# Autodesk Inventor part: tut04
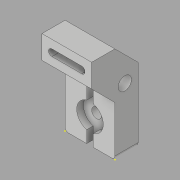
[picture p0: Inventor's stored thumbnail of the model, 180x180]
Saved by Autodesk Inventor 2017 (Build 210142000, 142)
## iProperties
Created: 2015-03
Part Number: tut04
Material: Generic
Document SubType Name: Modeling
Designer: Sandeep
Density: 1 g/cm^3
Appearance: Default
Author: Sandeep
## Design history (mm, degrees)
sketch "Sketch1"
  geometry: L1 (0, 0)-(0, 30); L2 (0, 30)-(-14, 44); L3 (-14, 44)-(-14, 58); L4 (-14, 58)-(0, 58); L5 (14, 44)-(14, 0); L6 (14, 0)-(0, 0); L7 (0, 58)-(14, 44)
  constraints: 14 end point, 3 parallel, 1 horizontal, 1 perpendicular, 1 vertical
  dimensions: "d0" = 14 distance between parallel lines of L5 L1; "d1" = 14 distance from line of L4.end L5; "d2" = 14 horizontal distance of L4.end L5.start; "d3" = 28 distance between parallel lines of L3 L5; "d4" = 58 distance between parallel lines of L4 L6; "d5" = 14 distance of L2.end L3.end
extrude "Extrusion1" new body sketch "Sketch1" distance "d6" = 30; taper "d7" = 0 deg
sketch "Sketch2"
  geometry: 1 further point
hole "Hole1" diameter "d10" = 8; stored, may be unused: countersink angle "d14" = 90 deg, drill point angle "d16" = 118 deg; dims "d8" = 21, "d9" = 8, "d11" = 6, "d12" = 4, "d13" = 2, "d15" = 8
sketch "Sketch3"
  geometry: L1 (0, 0)-(30, 0) reference; L2 (0, -30)-(30, -30) reference; L3 (30, 0)-(30, -30) reference; L4 (13, 0)-(13, -7.254); L5 (0, 3)-(30, 3) reference; L6 (17, 0)-(17, -7.254); L7 (15, -15)-(15, 7.075); L8 (13, 0)-(17, 0); L9 (-6.754, -15)-(33.848, -15); L10 (13, -22.746)-(13, -30); L11 (17, -30)-(17, -22.746); C1 r 3 at (15, -15); A1 r 8 centre (15, -15) between (13, -7.254) and (13, -22.746); A2 r 8 centre (15, -15) between (17, -22.746) and (17, -7.254)
  constraints: 14 end point, 5 point on line, 4 point on circle, 3 centre point, 2 parallel, 2 perpendicular, 1 coincident, 1 collinear, 1 horizontal, 1 vertical, 2 other
  dimensions: "d19" = 6 diameter of C1; "d21" = 15 distance from line of L2 A1.centre; "d22" = 15 distance from line of A1.centre L3; "d23" = 4 distance between parallel lines of L6 L4; "d24" = 4 distance between parallel lines of L11 L10; "d25" = 8 radius of A2; "d26" = 8 radius of A1
sketch "Sketch4"
  geometry: 1 further point
extrude "Extrusion2" cut sketch "Sketch3" distance "d27" = 4; taper "d28" = 0 deg
sketch "Sketch5"
  geometry: L1 (6, 7)-(24, 7); L2 (6, 5)-(24, 5); L3 (24, 9)-(6, 9); L4 (0, 14)-(30, 14) reference; L5 (30, 0)-(30, 14) reference; A1 r 2 centre (6, 7) between (6, 9) and (6, 5); A2 r 2 centre (24, 7) between (24, 5) and (24, 9); 2 further points
  constraints: 8 end point, 4 point on circle, 4 tangent, 2 centre point, 1 horizontal, 1 midpoint, 1 parallel
  dimensions: "d29" = 7 distance between parallel lines of L4 L1; "d30" = 18 distance of L1.start L1.end; "d31" = 6 distance from line of L5 L1.end; "d32" = 2 radius of A2
extrude "Extrusion3" cut sketch "Sketch5" distance "d33" = 11; taper "d34" = 0 deg
sketch "Sketch6"
  geometry: C1 r 3 at (0, 0); C2 r 3 at (0, 0) reference; 1 further point
  constraints: 1 centre point, 1 concentric
extrude "Extrusion4" cut sketch "Sketch6" distance "d35" = 35.25; taper "d36" = 0 deg
fillet "Fillet2" dims "d37" = 2
body "Solid1"
other parameters: "d20" = 16
